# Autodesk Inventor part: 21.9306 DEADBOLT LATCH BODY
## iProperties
Created: 2012-07
Part Number: 21.9306 DEADBOLT LATCH BODY
Document SubType Name: Modeling
Designer: Administrator
Density: 7.85 g/cm^3
Material: Cast Steel
Mass: 67.1037 g
Surface Area: 62.3143 cm^2
Volume: 8.54824 cm^3
Author: Administrator
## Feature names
1. Base1
